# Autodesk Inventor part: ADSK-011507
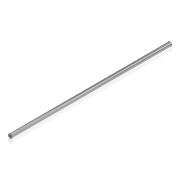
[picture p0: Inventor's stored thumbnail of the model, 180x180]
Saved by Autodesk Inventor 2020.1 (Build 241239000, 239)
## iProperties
Created: 2000-02
Part Number: ADSK-011507
Material: Pearson DGP
Description: SHFTTA,RG,AX,10,366,EE,SLIDE
Document SubType Name: Modeling
Designer: cmcgourin
Density: 7.83 g/cm^3
Appearance: Chrom - poliert
Mass: 3674.26 g
Surface Area: 789.128 cm^2
Volume: 469.254 cm^3
Control State: 0
Checked Out: False
Master: False
Shininess: 60.0
Length Units: 11269
Angle Units: 11279
Time Units: 11290
Mass Units: 11283
Length Display Precision: 3
Angle Display Precision: 2
Compacted: True
Cutlength: 36.69
Material Desc: ROUND,DGP, 1144,1.0000 DIA
Material_Number: A084577
Dimensions: 25x25x967 mm
Mass: 3,674 kg
DocNumber: ADSK-011507.ipt
Folder: 01 - Themengebiete\Simplification\01 - Packaging machine\
VDS_Category: 3D Komponenten
Density: 7.830000000000001
Volumn: 467.7841307431384
Area: 764.6736186179483
PropertySet Name: Model Information
Author: cmcgourin
Revision Number: -
Title: shaft
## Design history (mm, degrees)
node "Hole2" dims "d9" = 10.106, "d10" = 9.525, "d11" = 6.35, "d12" = 60 deg, "d13" = 32.3, "d14" = 118 deg, "d19" = 24
node "Chamfer1" dims "d15" = 1, "d16" = 1, "d17" = 45 deg
node "Solide1"
  node "Extrusion1" dims "d1" = 967, "d2" = 0
  node "Hole1" dims "d3" = 10.106, "d4" = 9.525, "d5" = 6.35, "d6" = 60 deg, "d7" = 32.3, "d8" = 118 deg, "d18" = 24
sketch "Sketch1"
  geometry: C1 r 12.5 at (0, 0); 2 further points
  constraints: 2 coincident, 1 centre point
  dimensions: "d0" = 25 diameter of C1
node "Corps solides"
node "Corps surfaciques"
sketch "Sketch2"
  geometry: C1 r 12.5 at (0, 0) reference; 1 further point
  constraints: 1 coincident
sketch "Sketch3"
  geometry: C1 r 12.5 at (0, 0) reference; 1 further point
  constraints: 1 coincident
